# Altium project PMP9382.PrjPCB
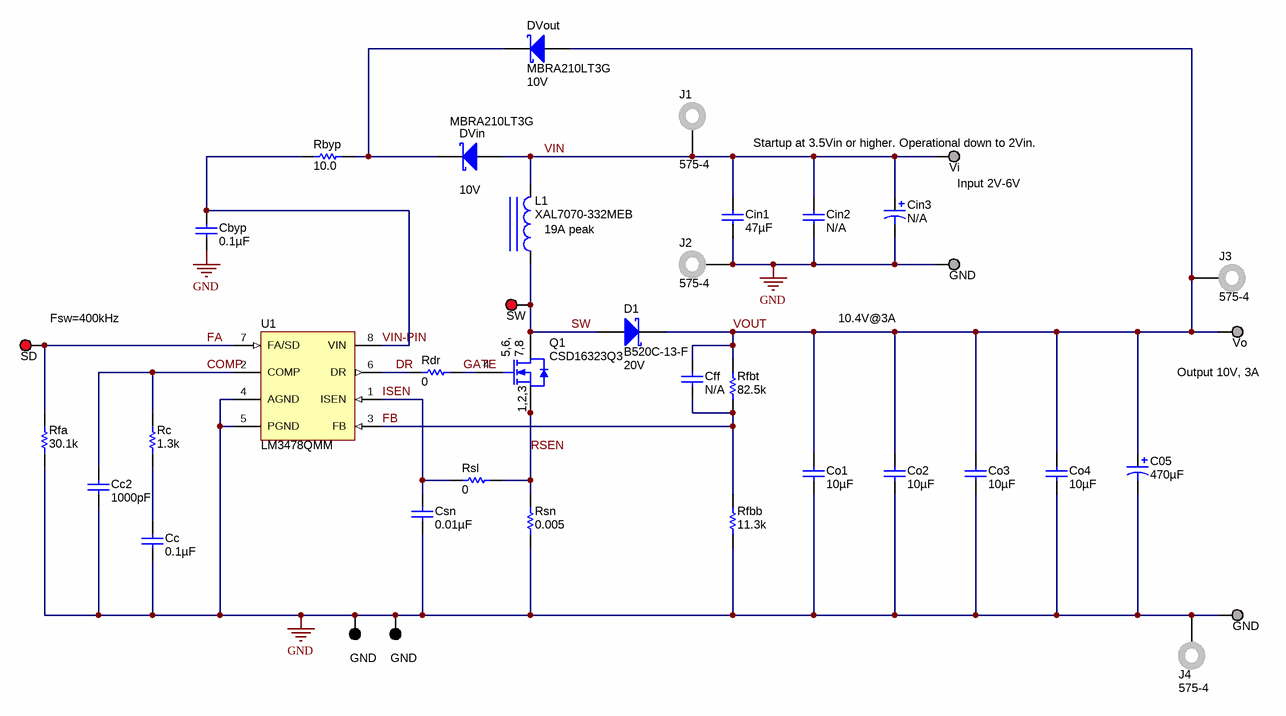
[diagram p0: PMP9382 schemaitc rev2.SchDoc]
CopyrightYear: 2014; PCB_Layout: N/A; PCB_Rev: A; PRJ_Customer: Public Release; PRJ_Engineer: D Baba; PRJ_Number: PMP9382; PRJ_Title: PMP9382 LM3478 Low Vin Boost; SCH_Rev: 2; TechSupport: http://www.ti.com/support
2 sheets, 46 parts. Net scope: global (net labels, ports and power ports of the same name join across sheets).
Board file: PMP9382.PcbDoc
Sheets:
  PMP9382 schemaitc rev2.SchDoc
  PMP9382_Hardware_ANSI-B.SchDoc

## Sheet PMP9382 schemaitc rev2.SchDoc
size 431 x 279 mm; Date: Not shown in title block; ApprovedBy: Not shown in title block; CheckedBy: Not shown in title block; Author: Not shown in title block; CompanyName: Not shown in title block; Engineer: Not shown in title block; Organization: Not shown in title block; Address1: Not shown in title block; Address2: Not shown in title block; Address3: Not shown in title block; Address4: Not shown in title block; DocumentNumber: 1; Revision: Use project parameter SCH_Rev; SheetNumber: 1; SheetTotal: 2; PageSetup: Record=PageOptions¦CenterHorizontal=True¦CenterVertical=True¦PrintScale=0.94¦XCorrection=1.00¦YCorrection=1.00¦PrintKind=0¦BorderSize=5000000¦LeftOffset=0¦BottomOffset=0¦Orientation=2¦PaperLength=1000¦PaperWidth=1000¦Scale=100¦PaperSource=15¦PrintQuality=600¦MediaType=1¦DitherType=10¦PaperKind=A3¦PrintScaleMode=1

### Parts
C05  ValueDisplayed: 470µF  [CAPSMT_62_JC0]  (hidden comment: 16SVPE470M)
Cbyp  ValueDisplayed: 0.1µF  [0603]  (hidden comment: GRM188R71C104KA01D)
Cc  ValueDisplayed: 0.1µF  [0805_HV]  (hidden comment: 08055C104JAT2A)
Cc2  ValueDisplayed: 1000pF  [0805_HV]  (hidden comment: 08055A102FAT2A)
Cff  C3216X5R1E476M  [0603]  (value not drawn)  (no BOM)
Cin1  ValueDisplayed: 47µF  [2220]  (hidden comment: C5750X5R1C476M)
Cin2  C3216X5R1E476M  [1206]  (value not drawn)  (no BOM)
Cin3  APXA160ARA331MJC0G  [CAPSMT_62_JC0]  (value not drawn)  (no BOM)
Co1  ValueDisplayed: 10µF  [0805_HV]  (hidden comment: EMK212BJ106KG-T)
Co2  ValueDisplayed: 10µF  [0805_HV]  (hidden comment: EMK212BJ106KG-T)
Co3  ValueDisplayed: 10µF  [0805_HV]  (hidden comment: EMK212BJ106KG-T)
Co4  ValueDisplayed: 10µF  [0805_HV]  (hidden comment: EMK212BJ106KG-T)
Csn  ValueDisplayed: 0.01µF  [0603]  (hidden comment: C0603C103K5RACTU)
D1  B520C-13-F  value 20V  [SMC]
DVin  MBRA210LT3G  value 10V  [SMA]
DVout  MBRA210LT3G  value 10V  [SMA]
J1  575-4  [Keystone_575-4]
J2  575-4  [Keystone_575-4]
J3  575-4  [Keystone_575-4]
J4  575-4  [Keystone_575-4]
L1  XAL7070-332MEB  Value2: 19A peak  [XAL7070]
Q1  CSD16323Q3  [TRANS_NexFET_Q3]
Rbyp  value 10.0  [0603]  (hidden comment: CRCW060310R0FKEA)
Rc  value 1.3k  [0805_HV]  (hidden comment: CRCW08051K30JNEA)
Rdr  value 0  [0603]  (hidden comment: CRCW06030000Z0EA)
Rfa  value 30.1k  [0805_HV]  (hidden comment: CRCW080530K1FKEA)
Rfbb  value 11.3k  [0805_HV]  (hidden comment: CRCW080511K3FKEA)
Rfbt  value 82.5k  [0805_HV]  (hidden comment: CRCW080582K5FKEA)
Rsl  value 0  [0603]  (hidden comment: CRCW06030000Z0EA)
Rsn  value 0.005  [3008M]  (hidden comment: RL7520WT-R005-F)
TP1  Vi  [Keystone1502-2]
TP2  GND  [Keystone1502-2]
TP3  SW  [Keystone5000]
TP4  Vo  [Keystone1502-2]
TP5  SD  [Keystone5000]
TP6  GND  [Keystone1502-2]
TP7  GND  [Keystone5001]
TP8  GND  [Keystone5001]
U1  LM3478QMM  [MUA08A_N]

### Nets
GND: C05.2(-) Cbyp.2 Cc.2 Cc2.2 Cin1.2 Cin2.2 Cin3.2(-) Co1.2 Co2.2 Co3.2 Co4.2 Csn.2 J2.1 J4.1 Rfa.1 Rfbb.1 Rsn.1 TP2.1 TP6.1 TP7.1 TP8.1 U1.4(AGND) U1.5(PGND)
COMP: Cc2.1 Rc.2 U1.2(COMP)
DR: Rdr.1 U1.6(DR)
FA: Rfa.2 TP5.1 U1.7(FA/SD)
FB: Cff.2 Rfbb.2 Rfbt.1 U1.3(FB)
GATE: Q1.4(G) Rdr.2
ISEN: Csn.1 Rsl.2 U1.1(ISEN)
RSEN: Q1.1(S) Q1.2(S) Q1.3(S) Rsl.1 Rsn.2
SW: D1.2(A) L1.1 Q1.5(D) Q1.6(D) Q1.7(D) Q1.8(D) TP3.1
VIN: Cin1.1 Cin2.1 Cin3.1(+) DVin.2(A) J1.1 L1.2 TP1.1
VIN-PIN: Cbyp.1 Rbyp.1 U1.8(VIN)
VOUT: C05.1(+) Cff.1 Co1.1 Co2.1 Co3.1 Co4.1 D1.1(K) DVout.2(A) J3.1 Rfbt.2 TP4.1
NetCc_1: Cc.1 Rc.1
NetDVin_1: DVin.1(K) DVout.1(K) Rbyp.2

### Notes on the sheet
- (near TP1) Startup at 3.5Vin or higher. Operational down to 2Vin.
- (near TP1) Input 2V-6V
- (near TP5) Fsw=400kHz
- 10.4V@3A
- (near TP4) Output 10V, 3A

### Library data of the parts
C05 = 16SVPE470M: CAP, AL, 470uF, 16V, +/-20%, 0.01 ohm, SMD; Manufacturer: Sanyo; Polarized: Y; CompType: Capacitor; U/M: EA; Cap_F: 0.00047; Tolerance_%: 20; VDC_V: 16; ESR_Ohm: 0.01; IRMS_A: 6.1; TaMin_C: -55; TaMax_C: 105
Cbyp = GRM188R71C104KA01D: CAP, CERM, 0.1uF, 16V, +/-10%, X7R, 0603; Manufacturer: MuRata; Polarized: N; TaMax_C: 125; TaMin_C: -55; Tolerance_%: 10; VDC_V: 16; Cap_F: 0.0000001; CompType: Capacitor; U/M: EA
Cc = 08055C104JAT2A: CAP, CERM, 0.1uF, 50V, +/-5%, X7R, 0805; Manufacturer: AVX; Polarized: N; CompType: Capacitor; U/M: EA; Cap_F: 0.0000001; Tolerance_%: 5; ESR_Ohm: 0.024; Value1: 0.024 ohm; VDC_V: 50; TaMin_C: -55; TaMax_C: 125; Cap_Case: 0805
Cc2 = 08055A102FAT2A: CAP, CERM, 1000pF, 50V, +/-1%, C0G/NP0, 0805; Manufacturer: AVX; Polarized: N; CompType: Capacitor; U/M: EA; Cap_F: 0.000000001; Tolerance_%: 1; ESR_Ohm: 0.112; Value1: 0.112 ohm; VDC_V: 50; TaMin_C: -55; TaMax_C: 125; Cap_Case: 0805
Cff Cin2 = Capacitor: CAP, CERM, 47uF, 25V, X5R, 1206; Manufacturer: Used in BOM report; Polarized: N; U/M: EA
Cin1 = C5750X5R1C476M: CAP, CERM, 47uF, 16V, +/-20%, X5R, 2220; Manufacturer: TDK; Polarized: N; CompType: Capacitor; U/M: EA; Cap_F: 0.000047; Tolerance_%: 20; ESR_Ohm: 0.004; Value1: 0.004 ohm; VDC_V: 16; IRMS_A: 2.1; TaMin_C: -55; TaMax_C: 85
Cin3 = APXA160ARA331MJC0G: CAP, AL, 330uF, 16V, +/-20%, 0.014 ohm, SMD; Manufacturer: Nippon Chemi-Con; Polarized: Y; CompType: Capacitor; U/M: EA; Cap_F: 0.00033; Tolerance_%: 20; VDC_V: 16; ESR_Ohm: 0.014; IRMS_A: 5.05; TaMin_C: -55; TaMax_C: 105; Cap_Case: JC0
Co1-Co4 = EMK212BJ106KG-T: CAP, CERM, 10uF, 16V, +/-10%, X5R, 0805; Manufacturer: Taiyo Yuden; Polarized: N; CompType: Capacitor; U/M: EA; Cap_F: 0.00001; Tolerance_%: 10; Value1: Unknown; VDC_V: 16; TaMin_C: -55; TaMax_C: 85; Cap_Case: 0805
Csn = C0603C103K5RACTU: CAP, CERM, 0.01uF, 50V, +/-10%, X7R, 0603; Manufacturer: Kemet; Polarized: N; TaMax_C: 125; TaMin_C: -55; Tolerance_%: 10; VDC_V: 50; Cap_F: 0.00000001; CompType: Capacitor; U/M: EA
D1 = B520C-13-F: Diode, Schottky, 20V, 5A, SMC; Manufacturer: Diodes Inc.; U/M: EA; Vf_V: 0.55; Value2: 0.55V; Io_A: 5; Vr_V: 20; TJmax_C: 125; RJC_CperW: 10
DVin DVout = MBRA210LT3G: Diode, Schottky, 10V, 2A, SMA; Manufacturer: ON Semiconductor; U/M: EA; Vf_V: 0.35; Value2: 0.35V; Io_A: 2; Vr_V: 10; TJmax_C: 125; RJC_CperW: 22
J1-J4 = 575-4: Standard Banana Jack, Uninsulated, 5.5mm; Manufacturer: Keystone; CompType: Connector; U/M: EA
L1 = XAL7070-332MEB: Inductor, Shielded, Composite, 3.3uH, 15.1A, 0.01 ohm, SMD; Manufacturer: Coilcraft; Ind_H: 3.3E-6; ValueDisplayed: 3.3µH; Imax_A: 15.1; Irms: 15.1A @ 40C rise; Isat: 19.4A @ 30% inductance drop; DCR_ohm: 0.01; U/M: EA
Q1 = CSD16323Q3: MOSFET, N-CH, 25V, 60A, SON 3.3x3.3mm; Manufacturer: Texas Instruments; Alternate Manufacturer: None; U/M: EA; ChType: N; VdsMax_V: 25; Value1: 0.0044 ohm; Rdson45_Ohm: 0.0044; Value2: 6.2 nC; QgTyp_nC: 6.2; Vgs_V: 10; IdsMax_A: 60
Rbyp = CRCW060310r0FKEA: RES, 10.0 ohm, 1%, 0.1W, 0603; Manufacturer: Vishay-Dale; CompType: Resistor; Tolerance_%: 1; VDC_V: 75; Power_W: 0.1; Res_ohm: 10; Value_Code: 10R0; EIA_Code: E96; U/M: EA; TempCo: 100 ppm/C
Rc = CRCW08051K30JNEA: RES, 1.3k ohm, 5%, 0.125W, 0805; Manufacturer: Vishay-Dale; CompType: Resistor; Res_ohm: 1300; Value_Code: 1k30; Tolerance_%: 5; Power_W: 0.125; VDC_V: 150; TempCo: 200 ppm/C; EIA_Code: E24; U/M: EA
Rdr Rsl = CRCW06030000Z0EA: RES, 0 ohm, 5%, 0.1W, 0603; Manufacturer: Vishay-Dale; CompType: Resistor; Tolerance_%: 5; VDC_V: 75; Power_W: 0.1; Value_Code: 0000; EIA_Code: E24; U/M: EA; TempCo: 200 ppm/C
Rfa = CRCW080530K1FKEA: RES, 30.1k ohm, 1%, 0.125W, 0805; Manufacturer: Vishay-Dale; CompType: Resistor; Res_ohm: 30100; Value_Code: 30k1; Tolerance_%: 1; Power_W: 0.125; VDC_V: 150; TempCo: 100 ppm/C; EIA_Code: E96; U/M: EA
Rfbb = CRCW080511K3FKEA: RES, 11.3k ohm, 1%, 0.125W, 0805; Manufacturer: Vishay-Dale; CompType: Resistor; Tolerance_%: 1; VDC_V: 150; Power_W: 0.125; Res_ohm: 11300; Value_Code: 11k3; EIA_Code: E96; U/M: EA; TempCo: 100 ppm/C
Rfbt = CRCW080582K5FKEA: RES, 82.5k ohm, 1%, 0.125W, 0805; Manufacturer: Vishay-Dale; CompType: Resistor; Res_ohm: 82500; Value_Code: 82k5; Tolerance_%: 1; Power_W: 0.125; VDC_V: 150; TempCo: 100 ppm/C; EIA_Code: E96; U/M: EA
Rsn = RL7520WT-R010-F: RES, 0.005 ohm, 1%, 2W, 3008; Manufacturer: Susumu Co Ltd; CompType: Resistor; Res_ohm: 0.01; Value_Code: R010; Tolerance_%: 1; Power_W: 2; TempCo: 350 ppm/C; EIA_Code: E96; U/M: EA
TP1 TP2 TP4 TP6 = 1502-2: Terminal, Turret, TH, Double; Manufacturer: Keystone Electronics; CompType: Turret Terminal; U/M: EA
TP3 TP5 = 5000: Test Point, TH, Miniature, Red; Manufacturer: Keystone Electronics; CompType: Test Point Loop; U/M: EA
TP7 TP8 = 5001: Test Point, TH, Miniature, Black; Manufacturer: Keystone; CompType: Test Point Loop; U/M: EA
U1 = LM3478QMM: High Efficiency Low-Side N-Channel Controller for Switching Regulator, Automotive Grade 1, 8-pin MSOP; Manufacturer: Texas Instruments; PackageTopMarking: ZXTT*SSFB; PowerWise: N; CompType: MiscPower

## Sheet PMP9382_Hardware_ANSI-B.SchDoc
size 431 x 279 mm; Date: Not shown in title block; ApprovedBy: Not shown in title block; CheckedBy: Not shown in title block; Author: Not shown in title block; CompanyName: Not shown in title block; Engineer: Not shown in title block; Organization: Not shown in title block; Address1: Not shown in title block; Address2: Not shown in title block; Address3: Not shown in title block; Address4: Not shown in title block; DocumentNumber: 2; Revision: Use project parameter SCH_Rev; SheetNumber: 2; SheetTotal: 2; PageSetup: Record=PageOptions¦CenterHorizontal=True¦CenterVertical=True¦PrintScale=1.00¦XCorrection=1.00¦YCorrection=1.00¦PrintKind=0¦BorderSize=5000000¦LeftOffset=0¦BottomOffset=0¦Orientation=2¦PaperLength=1000¦PaperWidth=1000¦Scale=100¦PaperSource=15¦PrintQuality=600¦MediaType=1¦DitherType=10¦PaperKind=Letter¦PrintScaleMode=1
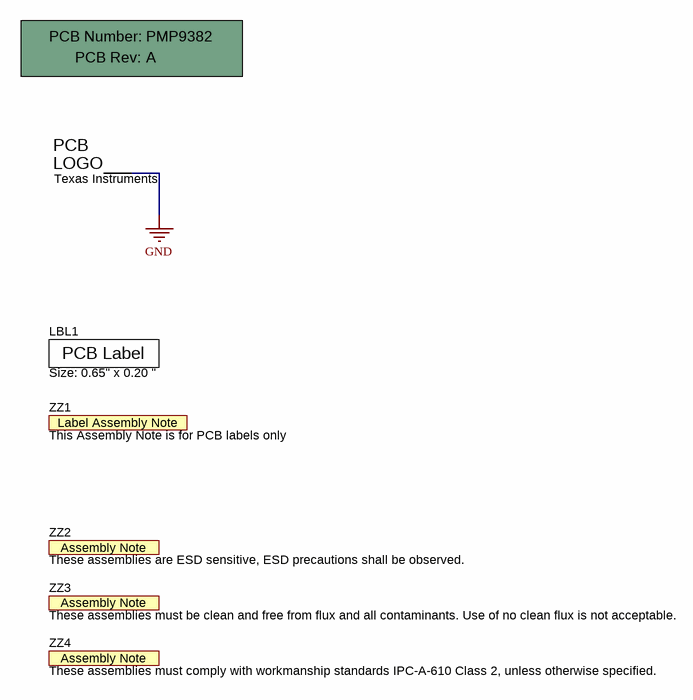
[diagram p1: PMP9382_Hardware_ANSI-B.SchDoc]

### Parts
!PCB  Printed Circuit Board  (value not drawn)  (mechanical)
LBL1  Size: 0.65" x 0.20 "  [Label_650x200]
Logo1  Texas Instruments  [TI_Stacked_SolderMask_Small]  (no BOM)
ZZ1  This Assembly Note is for PCB labels only  [AssemblyNoteLabel]  (no BOM)
ZZ2  These assemblies are ESD sensitive, ESD precautions shall be observed.  [AssemblyNote]  (no BOM)
ZZ3  These assemblies must be clean and free from flux and all contaminants. Use of no clean flux is not acceptable.  [AssemblyNote]  (no BOM)
ZZ4  These assemblies must comply with workmanship standards IPC-A-610 Class 2, unless otherwise specified.  [AssemblyNote]  (no BOM)

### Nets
GND: Logo1.0

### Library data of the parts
!PCB = PCB: Manufacturer: Any; PartNumber: PMP9382; SymbolCreator: a0412235
LBL1 = THT-14-423-10: Thermal Transfer Printable Labels, 0.650" W x 0.200" H - 10,000 per roll; Manufacturer: Brady; SymbolCreator: a0412235; CompType: Label
Logo1 = TI_Logo: Texas Instrument Corporate Signature; SymbolCreator: codlsc
ZZ1 = AssemblyNoteLabel: SymbolCreator: a0412235
ZZ2-ZZ4 = AssemblyNote: SymbolCreator: codlsc

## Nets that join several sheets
GND: PMP9382 schemaitc rev2 (23 pins), PMP9382_Hardware_ANSI-B (Logo1.0)

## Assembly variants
001: not fitted Cff Cin2 Cin3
